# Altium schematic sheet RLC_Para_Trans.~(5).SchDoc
size A4
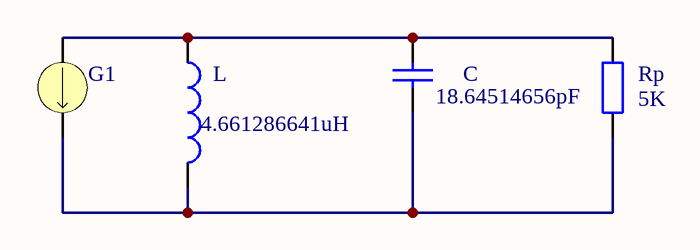
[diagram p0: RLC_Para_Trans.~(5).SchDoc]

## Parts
C  value 18.64514656pF  [RAD-0.3]  (hidden comment: Cap)
G1  ISRC  (value not drawn)
L  value 4.661286641uH  [0402-A]  (hidden comment: Inductor)
Rp  value 5K  [AXIAL-0.4]  (hidden comment: Res2)

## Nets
NetC_1: C.1 G1.2 L.2 Rp.1
NetC_2: C.2 G1.1 L.1 Rp.2

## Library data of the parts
C = Cap: Capacitor
G1 = ISRC: Current Source; Note: PCB Footprint - Not required; Value: 1mA
L = Inductor: Code_IEC: 1005
Rp = Res2: Resistor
